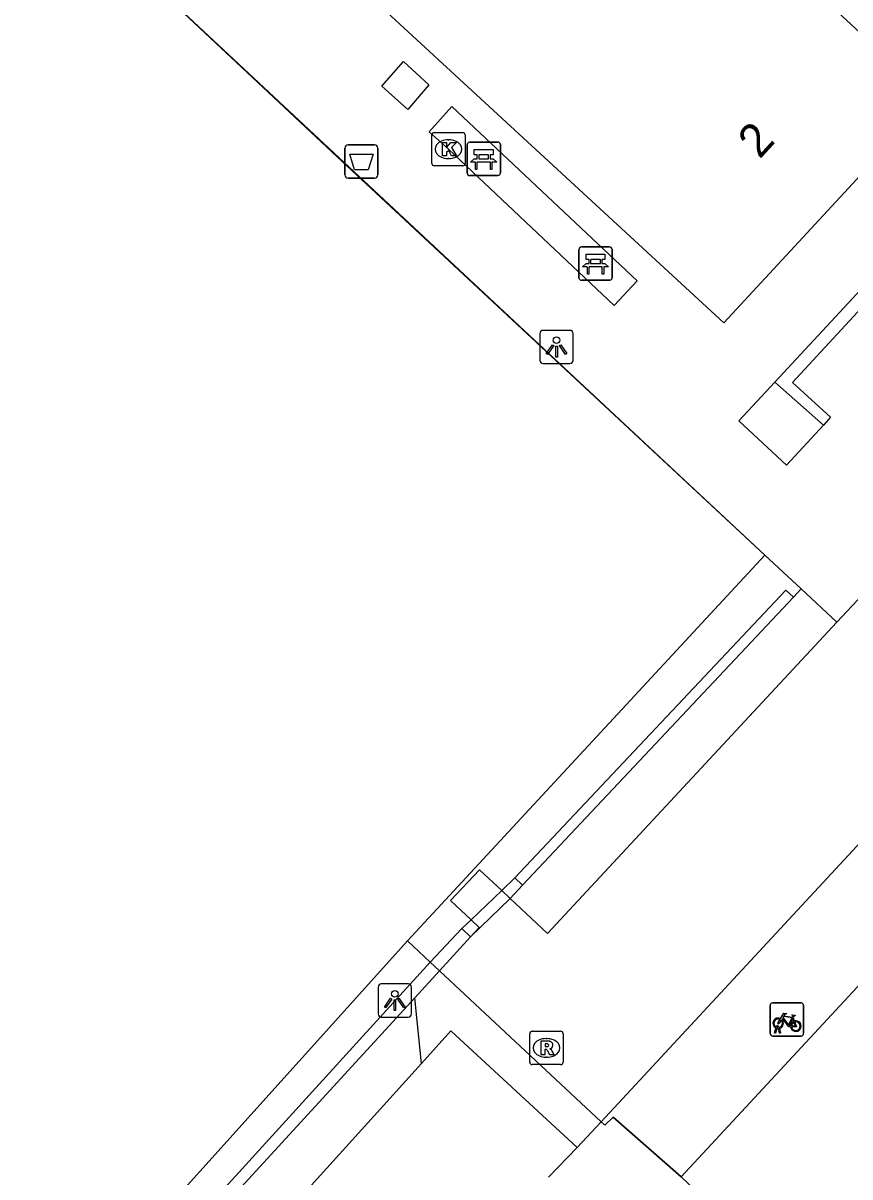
# Model space of a CAD drawing. Extents: x 155640 to 156810, y 382822 to 384046.
# Drawn here: x 156212.63 to 156237.43, y 383263.35 to 383297.97 of the extents above; entities that cross this region are included whole.
import ezdxf

# ---------------------------------------------------------------- set-up
doc = ezdxf.new("R2010")
doc.units = 0
for name, color, linetype in [('IMGEO_Afvalbak', 7, 'Continuous'), ('IMGEO_Bank', 7, 'Continuous'), ('IMGEO_Fietsenrek', 7, 'Continuous'), ('IMGEO_Groenvoorziening', 7, 'Continuous'), ('IMGEO_Haag', 7, 'Continuous'), ('IMGEO_Hek', 7, 'Continuous'), ('IMGEO_Kolk', 7, 'Continuous'), ('IMGEO_Lichtpunt', 7, 'Continuous'), ('IMGEO_Pand', 7, 'Continuous'), ('IMGEO_Pand_nummerreeks', 7, 'Continuous'), ('IMGEO_Rijbaan_lokaal_gesloten', 7, 'Continuous'), ('IMGEO_Rioolput', 7, 'Continuous'), ('IMGEO_Voetpad_op_trap', 7, 'Continuous'), ('IMGEO_Voetpad_open', 7, 'Continuous')]:
    doc.layers.add(name, color=color, linetype=linetype)

msp = doc.modelspace()

# ---------------------------------------------------------------- linework, layer by layer
at = {"layer": 'IMGEO_Afvalbak'}
for p, q in [((156222.383, 383294.317), (156223.173, 383294.317)), ((156223.173, 383294.317), (156222.383, 383294.317)), ((156222.283, 383293.417), (156222.283, 383294.217)), ((156222.283, 383294.217), (156222.283, 383293.417)), ((156223.273, 383294.217), (156223.273, 383293.417)), ((156223.273, 383293.417), (156223.273, 383294.217)), ((156223.173, 383293.317), (156222.383, 383293.317)), ((156222.383, 383293.317), (156223.173, 383293.317))]:
    msp.add_line(p, q, dxfattribs=at)
msp.add_lwpolyline([(156222.426, 383294.031), (156223.13, 383294.031), (156222.981, 383293.561), (156222.575, 383293.561), (156222.426, 383294.031)], dxfattribs=at)
for centre, start, end in [((156222.383, 383294.217), 90, 180), ((156222.383, 383294.217), 90, 180), ((156223.173, 383294.217), 0, 90), ((156223.173, 383294.217), 360, 90), ((156222.383, 383293.417), 180, 270), ((156222.383, 383293.417), 180, 270), ((156223.173, 383293.417), 270, 0), ((156223.173, 383293.417), 270, 0)]:
    msp.add_arc(centre, 0.1, start, end, dxfattribs=at)
at = {"layer": 'IMGEO_Bank'}
for p, q in [((156225.946, 383293.471), (156225.946, 383294.312)), ((156225.946, 383294.312), (156225.946, 383293.471)), ((156226.021, 383294.396), (156226.862, 383294.396)), ((156226.862, 383294.396), (156226.021, 383294.396)), ((156226.946, 383294.321), (156226.946, 383293.48)), ((156226.946, 383293.48), (156226.946, 383294.321)), ((156226.255, 383293.902), (156226.255, 383294.008)), ((156226.299, 383294.008), (156226.299, 383293.902)), ((156226.587, 383294.014), (156226.305, 383294.014)), ((156226.593, 383293.902), (156226.593, 383294.008)), ((156226.637, 383294.008), (156226.637, 383293.902)), ((156226.643, 383293.794), (156226.25, 383293.794)), ((156226.305, 383293.896), (156226.587, 383293.896)), ((156226.871, 383293.396), (156226.03, 383293.396)), ((156226.03, 383293.396), (156226.871, 383293.396)), ((156229.301, 383290.328), (156229.301, 383291.169)), ((156229.301, 383291.169), (156229.301, 383290.328)), ((156229.376, 383291.253), (156230.217, 383291.253)), ((156230.217, 383291.253), (156229.376, 383291.253)), ((156230.301, 383291.178), (156230.301, 383290.337)), ((156230.301, 383290.337), (156230.301, 383291.178)), ((156229.61, 383290.759), (156229.61, 383290.865)), ((156229.654, 383290.865), (156229.654, 383290.759)), ((156229.942, 383290.871), (156229.66, 383290.871)), ((156229.948, 383290.759), (156229.948, 383290.865)), ((156229.992, 383290.865), (156229.992, 383290.759)), ((156229.998, 383290.651), (156229.605, 383290.651)), ((156229.66, 383290.753), (156229.942, 383290.753)), ((156230.226, 383290.253), (156229.385, 383290.253)), ((156229.385, 383290.253), (156230.226, 383290.253))]:
    msp.add_line(p, q, dxfattribs=at)
for points in [[(156226.249, 383294.014), (156226.163, 383294.014), (156226.163, 383294.175), (156226.726, 383294.175), (156226.726, 383294.014), (156226.643, 383294.014)], [(156226.193, 383293.794), (156226.051, 383293.794), (156226.163, 383293.896), (156226.249, 383293.896)], [(156226.243, 383293.787), (156226.243, 383293.58), (156226.2, 383293.58), (156226.2, 383293.787)], [(156226.643, 383293.896), (156226.726, 383293.896), (156226.838, 383293.794), (156226.699, 383293.794)], [(156226.693, 383293.787), (156226.693, 383293.58), (156226.649, 383293.58), (156226.649, 383293.787)], [(156229.604, 383290.871), (156229.518, 383290.871), (156229.518, 383291.032), (156230.081, 383291.032), (156230.081, 383290.871), (156229.998, 383290.871)], [(156229.548, 383290.651), (156229.406, 383290.651), (156229.518, 383290.753), (156229.604, 383290.753)], [(156229.598, 383290.644), (156229.598, 383290.437), (156229.555, 383290.437), (156229.555, 383290.644)], [(156229.998, 383290.753), (156230.081, 383290.753), (156230.193, 383290.651), (156230.054, 383290.651)], [(156230.048, 383290.644), (156230.048, 383290.437), (156230.004, 383290.437), (156230.004, 383290.644)]]:
    msp.add_lwpolyline(points, dxfattribs=at)
for centre, radius, start, end in [((156226.024, 383294.318), 0.0779, 92.4484, 184.2845), ((156226.024, 383294.318), 0.0779, 92.4484, 184.2845), ((156226.868, 383294.318), 0.0779, 2.4484, 94.2845), ((156226.868, 383294.318), 0.0779, 2.4484, 94.2845), ((156226.248, 383294.007), 0.00671, 2.8957, 87.1043), ((156226.305, 383294.007), 0.00671, 92.8957, 177.1043), ((156226.587, 383294.007), 0.00671, 2.8957, 87.1043), ((156226.644, 383294.007), 0.00671, 92.8957, 177.1043), ((156226.193, 383293.787), 0.00671, 2.8957, 87.1043), ((156226.25, 383293.787), 0.00671, 92.8957, 177.1043), ((156226.248, 383293.903), 0.00671, 272.8957, 357.1043), ((156226.305, 383293.903), 0.00671, 182.8957, 267.1043), ((156226.587, 383293.903), 0.00671, 272.8957, 357.1043), ((156226.644, 383293.903), 0.00671, 182.8957, 267.1043), ((156226.642, 383293.787), 0.00671, 2.8957, 87.1043), ((156226.699, 383293.787), 0.00671, 92.8957, 177.1043), ((156226.024, 383293.474), 0.0779, 182.4484, 274.2845), ((156226.024, 383293.474), 0.0779, 182.4484, 274.2845), ((156226.868, 383293.474), 0.0779, 272.4484, 4.2845), ((156226.868, 383293.474), 0.0779, 272.4484, 4.2845), ((156229.379, 383291.175), 0.0779, 92.4484, 184.2845), ((156229.379, 383291.175), 0.0779, 92.4484, 184.2845), ((156230.223, 383291.175), 0.0779, 2.4484, 94.2845), ((156230.223, 383291.175), 0.0779, 2.4484, 94.2845), ((156229.603, 383290.864), 0.00671, 2.8957, 87.1043), ((156229.66, 383290.864), 0.00671, 92.8957, 177.1043), ((156229.942, 383290.864), 0.00671, 2.8957, 87.1043), ((156229.999, 383290.864), 0.00671, 92.8957, 177.1043), ((156229.548, 383290.644), 0.00671, 2.8957, 87.1043), ((156229.605, 383290.644), 0.00671, 92.8957, 177.1043), ((156229.603, 383290.76), 0.00671, 272.8957, 357.1043), ((156229.66, 383290.76), 0.00671, 182.8957, 267.1043), ((156229.942, 383290.76), 0.00671, 272.8957, 357.1043), ((156229.999, 383290.76), 0.00671, 182.8957, 267.1043), ((156229.997, 383290.644), 0.00671, 2.8957, 87.1043), ((156230.054, 383290.644), 0.00671, 92.8957, 177.1043), ((156229.379, 383290.331), 0.0779, 182.4484, 274.2845), ((156229.379, 383290.331), 0.0779, 182.4484, 274.2845), ((156230.223, 383290.331), 0.0779, 272.4484, 4.2845), ((156230.223, 383290.331), 0.0779, 272.4484, 4.2845)]:
    msp.add_arc(centre, radius, start, end, dxfattribs=at)
at = {"layer": 'IMGEO_Fietsenrek'}
for p, q in [((156235.04, 383267.65), (156235.04, 383268.491)), ((156235.04, 383268.491), (156235.04, 383267.65)), ((156235.115, 383268.575), (156235.956, 383268.575)), ((156235.956, 383268.575), (156235.115, 383268.575)), ((156236.04, 383268.5), (156236.04, 383267.659)), ((156236.04, 383267.659), (156236.04, 383268.5)), ((156235.727, 383268.124), (156235.763, 383268.029)), ((156235.167, 383267.659), (156235.206, 383267.819)), ((156235.201, 383267.659), (156235.167, 383267.659)), ((156235.236, 383267.807), (156235.201, 383267.659)), ((156235.278, 383267.831), (156235.277, 383267.835)), ((156235.319, 383267.659), (156235.285, 383267.801)), ((156235.309, 383267.842), (156235.31, 383267.835)), ((156235.317, 383267.805), (156235.352, 383267.659)), ((156235.352, 383267.659), (156235.319, 383267.659)), ((156235.965, 383267.575), (156235.124, 383267.575)), ((156235.124, 383267.575), (156235.965, 383267.575))]:
    msp.add_line(p, q, dxfattribs=at)
for points in [[(156235.374, 383268.049), (156235.322, 383267.959), (156235.282, 383267.934), (156235.283, 383267.981), (156235.338, 383268.075)], [(156235.353, 383268.101), (156235.448, 383268.265), (156235.534, 383268.251), (156235.536, 383268.242), (156235.48, 383268.231), (156235.453, 383268.186), (156235.709, 383268.145)], [(156235.649, 383267.857), (156235.599, 383267.857), (156235.408, 383268.108), (156235.389, 383268.076)], [(156235.696, 383268.12), (156235.439, 383268.161), (156235.422, 383268.132), (156235.589, 383267.912), (156235.696, 383268.12)], [(156235.744, 383268.022), (156235.714, 383268.099), (156235.605, 383267.881), (156235.648, 383267.881)], [(156235.678, 383267.881), (156235.798, 383267.88), (156235.754, 383267.994)], [(156235.774, 383268.001), (156235.829, 383267.856), (156235.679, 383267.856)], [(156235.709, 383268.145), (156235.734, 383268.194), (156235.728, 383268.198), (156235.705, 383268.202), (156235.693, 383268.209), (156235.692, 383268.212), (156235.694, 383268.217), (156235.789, 383268.202), (156235.791, 383268.192), (156235.781, 383268.179), (156235.769, 383268.173), (156235.755, 383268.179), (156235.727, 383268.124)]]:
    msp.add_lwpolyline(points, dxfattribs=at)
for centre, radius, start, end in [((156235.118, 383268.497), 0.0779, 92.4484, 184.2845), ((156235.118, 383268.497), 0.0779, 92.4484, 184.2845), ((156235.962, 383268.497), 0.0779, 2.4484, 94.2845), ((156235.962, 383268.497), 0.0779, 2.4484, 94.2845), ((156235.28, 383267.96), 0.159, 62.6766, 242.1369), ((156235.28, 383267.96), 0.129, 63.3192, 238.903), ((156235.28, 383267.96), 0.129, 283.6043, 43.4302), ((156235.28, 383267.96), 0.159, 283.5766, 46.6042), ((156235.807, 383267.876), 0.159, 113.3408, 178.3217), ((156235.807, 383267.876), 0.159, 187.0065, 105.7708), ((156235.807, 383267.876), 0.129, 113.923, 177.9556), ((156235.807, 383267.876), 0.129, 188.6715, 104.5883), ((156235.118, 383267.653), 0.0779, 182.4484, 274.2845), ((156235.118, 383267.653), 0.0779, 182.4484, 274.2845), ((156235.26, 383267.831), 0.0499, 12.8025, 158.6934), ((156235.28, 383267.96), 0.159, 253.9967, 271.7867), ((156235.26, 383267.831), 0.0174, 12.8025, 163.4502), ((156235.28, 383267.96), 0.129, 253.415, 269.0204), ((156235.962, 383267.653), 0.0779, 272.4484, 4.2845), ((156235.962, 383267.653), 0.0779, 272.4484, 4.2845)]:
    msp.add_arc(centre, radius, start, end, dxfattribs=at)
at = {"layer": 'IMGEO_Groenvoorziening'}
for points in [[(156207.982, 383307.154), (156184.491, 383281.756), (156211.6, 383256.492), (156224.158, 383270.431)], [(156224.158, 383270.431), (156234.882, 383282.008)], [(156235.74, 383280.744), (156235.974, 383280.991)], [(156224.158, 383270.431), (156224.842, 383269.791)], [(156282.79, 383263.589), (156259.014, 383237.928), (156232.367, 383263.357)]]:
    msp.add_lwpolyline(points, dxfattribs=at)
at = {"layer": 'IMGEO_Haag'}
for points in [[(156224.842, 383269.791), (156210.619, 383254.175), (156181.633, 383280.902)], [(156227.383, 383272.321), (156235.514, 383280.957), (156235.74, 383280.744)], [(156227.61, 383272.109), (156235.74, 383280.744)], [(156226.987, 383271.944), (156227.383, 383272.321)], [(156227.241, 383271.705), (156227.61, 383272.109)], [(156227.61, 383272.109), (156227.383, 383272.321)], [(156225.79, 383270.803), (156226.067, 383271.067)], [(156224.842, 383269.791), (156225.79, 383270.803)], [(156225.79, 383270.803), (156226.054, 383270.555)], [(156225.119, 383269.532), (156224.842, 383269.791)], [(156210.637, 383253.749), (156224.377, 383268.721)]]:
    msp.add_lwpolyline(points, dxfattribs=at)
at = {"layer": 'IMGEO_Hek'}
for points in [[(156224.158, 383270.431), (156211.6, 383256.492), (156184.491, 383281.756), (156207.982, 383307.154)], [(156214.588, 383300.953), (156234.882, 383282.008)], [(156232.367, 383263.357), (156255.829, 383288.633), (156268.652, 383276.721)], [(156224.158, 383270.431), (156234.882, 383282.008)], [(156224.158, 383270.431), (156224.842, 383269.791)], [(156224.842, 383269.791), (156225.119, 383269.532)], [(156225.119, 383269.532), (156229.968, 383265.006)], [(156229.968, 383265.006), (156230.078, 383264.903), (156230.326, 383265.146), (156232.367, 383263.357)], [(156282.79, 383263.589), (156259.014, 383237.928), (156232.367, 383263.357)]]:
    msp.add_lwpolyline(points, dxfattribs=at)
at = {"layer": 'IMGEO_Kolk'}
for p, q in [((156224.89, 383293.759), (156224.89, 383294.611)), ((156224.965, 383294.685), (156225.817, 383294.685)), ((156225.891, 383294.611), (156225.891, 383293.759)), ((156225.378, 383294.465), (156225.403, 383294.465)), ((156225.817, 383293.685), (156224.965, 383293.685)), ((156225.401, 383293.905), (156225.376, 383293.905))]:
    msp.add_line(p, q, dxfattribs=at)
for points in [[(156224.89, 383293.759), (156224.89, 383294.611)], [(156224.965, 383294.685), (156225.817, 383294.685)], [(156225.891, 383294.611), (156225.891, 383293.759)], [(156225.211, 383294.385), (156225.334, 383294.385), (156225.334, 383294.234), (156225.464, 383294.385), (156225.628, 383294.385), (156225.482, 383294.234), (156225.635, 383293.985), (156225.483, 383293.985), (156225.398, 383294.149), (156225.334, 383294.082), (156225.334, 383293.985), (156225.211, 383293.985), (156225.211, 383294.385)], [(156225.817, 383293.685), (156224.965, 383293.685)]]:
    msp.add_lwpolyline(points, dxfattribs=at)
for centre, start, end in [((156224.967, 383294.609), 91.552, 178.448), ((156224.967, 383294.609), 91.552, 178.448), ((156225.815, 383294.609), 1.552, 88.448), ((156225.815, 383294.609), 1.552, 88.448), ((156224.967, 383293.761), 181.552, 268.448), ((156224.967, 383293.761), 181.552, 268.448), ((156225.815, 383293.761), 271.552, 358.448), ((156225.815, 383293.761), 271.552, 358.448)]:
    msp.add_arc(centre, 0.0765, start, end, dxfattribs=at)
for centre, major_axis, ratio, start_param, end_param in [((156225.377, 383294.185), (-0.387, 0.002), 0.722429, 4.712389, 7.853982), ((156225.402, 383294.185), (-0.39, 0.002), 0.717154, 1.570796, 4.712389)]:
    msp.add_ellipse(centre, major_axis=major_axis, ratio=ratio, start_param=start_param, end_param=end_param, dxfattribs=at)
at = {"layer": 'IMGEO_Lichtpunt'}
for p, q in [((156229.035, 383288.75), (156228.227, 383288.75)), ((156229.035, 383288.75), (156228.227, 383288.75)), ((156228.133, 383288.655), (156228.133, 383287.848)), ((156228.133, 383288.655), (156228.133, 383287.848)), ((156229.129, 383287.848), (156229.129, 383288.655)), ((156229.129, 383287.848), (156229.129, 383288.655)), ((156228.227, 383287.754), (156229.035, 383287.754)), ((156228.227, 383287.754), (156229.035, 383287.754)), ((156223.28, 383269.047), (156223.28, 383268.24)), ((156223.28, 383269.047), (156223.28, 383268.24)), ((156224.182, 383269.142), (156223.374, 383269.142)), ((156224.182, 383269.142), (156223.374, 383269.142)), ((156224.276, 383268.24), (156224.276, 383269.047)), ((156224.276, 383268.24), (156224.276, 383269.047)), ((156223.374, 383268.146), (156224.182, 383268.146)), ((156223.374, 383268.146), (156224.182, 383268.146))]:
    msp.add_line(p, q, dxfattribs=at)
for points in [[(156228.507, 383288.319), (156228.546, 383288.291), (156228.358, 383288.029), (156228.32, 383288.056), (156228.507, 383288.319)], [(156228.609, 383288.271), (156228.656, 383288.271), (156228.656, 383287.949), (156228.609, 383287.949), (156228.609, 383288.271)], [(156228.719, 383288.291), (156228.757, 383288.318), (156228.944, 383288.056), (156228.905, 383288.028), (156228.719, 383288.291)], [(156223.654, 383268.711), (156223.693, 383268.683), (156223.505, 383268.421), (156223.467, 383268.448), (156223.654, 383268.711)], [(156223.756, 383268.663), (156223.803, 383268.663), (156223.803, 383268.341), (156223.756, 383268.341), (156223.756, 383268.663)], [(156223.866, 383268.683), (156223.904, 383268.71), (156224.091, 383268.448), (156224.052, 383268.42), (156223.866, 383268.683)]]:
    msp.add_lwpolyline(points, dxfattribs=at)
for centre in [(156228.632, 383288.453), (156223.779, 383268.845)]:
    msp.add_circle(centre, 0.0994, dxfattribs=at)
for centre, start, end in [((156228.227, 383288.655), 90, 180), ((156228.227, 383288.655), 90, 180), ((156229.035, 383288.655), 0, 90), ((156229.035, 383288.655), 0, 90), ((156228.227, 383287.848), 180, 270), ((156228.227, 383287.848), 180, 270), ((156229.035, 383287.848), 270, 0), ((156229.035, 383287.848), 270, 360), ((156223.374, 383269.047), 90, 180), ((156223.374, 383269.047), 90, 180), ((156224.182, 383269.047), 0, 90), ((156224.182, 383269.047), 0, 90), ((156223.374, 383268.24), 180, 270), ((156223.374, 383268.24), 180, 270), ((156224.182, 383268.24), 270, 0), ((156224.182, 383268.24), 270, 360)]:
    msp.add_arc(centre, 0.0946, start, end, dxfattribs=at)
at = {"layer": 'IMGEO_Pand'}
msp.add_lwpolyline([(156230.318, 383303.16), (156230.424, 383303.062), (156231.102, 383303.797), (156232.207, 383302.778), (156237.342, 383298.044), (156239.878, 383295.706), (156233.654, 383288.973), (156222.769, 383299.019)], dxfattribs=at)
at = {"layer": 'IMGEO_Rijbaan_lokaal_gesloten'}
for points in [[(156229.248, 383264.232), (156225.464, 383267.736), (156224.577, 383266.755)], [(156224.577, 383266.755), (156215.589, 383256.815)], [(156228.393, 383263.345), (156229.248, 383264.232)]]:
    msp.add_lwpolyline(points, dxfattribs=at)
at = {"layer": 'IMGEO_Rioolput'}
for p, q in [((156227.827, 383266.795), (156227.827, 383267.647)), ((156227.902, 383267.721), (156228.754, 383267.721)), ((156228.828, 383267.647), (156228.828, 383266.795)), ((156228.315, 383267.501), (156228.34, 383267.501)), ((156228.338, 383266.941), (156228.313, 383266.941)), ((156228.754, 383266.721), (156227.902, 383266.721))]:
    msp.add_line(p, q, dxfattribs=at)
for points in [[(156227.827, 383266.795), (156227.827, 383267.647)], [(156227.902, 383267.721), (156228.754, 383267.721)], [(156228.828, 383267.647), (156228.828, 383266.795)], [(156228.416, 383267.419), (156228.164, 383267.421), (156228.164, 383267.021)], [(156228.342, 383267.34), (156228.288, 383267.34), (156228.288, 383267.259)], [(156228.288, 383267.259), (156228.34, 383267.259)], [(156228.164, 383267.021), (156228.288, 383267.021), (156228.288, 383267.183), (156228.299, 383267.183)], [(156228.346, 383267.154), (156228.417, 383267.021), (156228.557, 383267.021), (156228.492, 383267.147)], [(156228.754, 383266.721), (156227.902, 383266.721)]]:
    msp.add_lwpolyline(points, dxfattribs=at)
for centre, radius, start, end in [((156227.904, 383267.645), 0.0765, 91.552, 178.448), ((156227.904, 383267.645), 0.0765, 91.552, 178.448), ((156228.752, 383267.645), 0.0765, 1.552, 88.448), ((156228.752, 383267.645), 0.0765, 1.552, 88.448), ((156228.324, 383267.448), 0.19, 274.7715, 282.9687), ((156228.348, 383267.244), 0.0964, 77.0061, 93.1865), ((156228.362, 383267.301), 0.0378, 276.6634, 79.6772), ((156228.415, 383267.309), 0.109, 350.3612, 89.416), ((156228.413, 383267.309), 0.112, 277.5842, 350.9817), ((156228.298, 383267.13), 0.0533, 26.0293, 88.6989), ((156228.397, 383267.094), 0.108, 29.5134, 73.7905), ((156227.904, 383266.797), 0.0765, 181.552, 268.448), ((156227.904, 383266.797), 0.0765, 181.552, 268.448), ((156228.752, 383266.797), 0.0765, 271.552, 358.448), ((156228.752, 383266.797), 0.0765, 271.552, 358.448)]:
    msp.add_arc(centre, radius, start, end, dxfattribs=at)
for centre, major_axis, ratio, start_param, end_param in [((156228.314, 383267.221), (-0.387, 0.002), 0.722429, 4.712389, 7.853982), ((156228.339, 383267.221), (-0.39, 0.002), 0.717154, 1.570796, 4.712389)]:
    msp.add_ellipse(centre, major_axis=major_axis, ratio=ratio, start_param=start_param, end_param=end_param, dxfattribs=at)
at = {"layer": 'IMGEO_Voetpad_op_trap'}
msp.add_lwpolyline([(156236.64, 383285.907), (156235.177, 383287.192)], dxfattribs=at)
at = {"layer": 'IMGEO_Voetpad_open'}
for points in [[(156214.588, 383300.953), (156222.047, 383293.953), (156234.882, 383282.008)], [(156253.325, 383297.342), (156237.042, 383279.998)], [(156224.166, 383295.376), (156223.394, 383296.071), (156224.037, 383296.818), (156224.798, 383296.115), (156224.166, 383295.376)], [(156231.052, 383290.231), (156230.356, 383289.496), (156225.392, 383294.186), (156224.813, 383294.706), (156225.486, 383295.467), (156231.052, 383290.231)], [(156256.953, 383294.104), (156229.968, 383265.006)], [(156235.177, 383287.192), (156240.872, 383293.328)], [(156242.291, 383292.016), (156242.011, 383291.724), (156240.833, 383292.73), (156235.707, 383287.185), (156236.846, 383286.147), (156236.64, 383285.907)], [(156232.367, 383263.357), (156255.829, 383288.633), (156268.652, 383276.721), (156269.946, 383275.518), (156276.075, 383269.864)], [(156236.64, 383285.907), (156235.527, 383284.709), (156234.099, 383286.031), (156235.177, 383287.192)], [(156234.882, 383282.008), (156235.974, 383280.991)], [(156235.974, 383280.991), (156237.042, 383279.998)], [(156237.042, 383279.998), (156228.361, 383270.65), (156227.241, 383271.705)], [(156226.987, 383271.944), (156226.325, 383272.567), (156225.455, 383271.643), (156226.067, 383271.067)], [(156226.987, 383271.944), (156226.067, 383271.067)], [(156227.241, 383271.705), (156226.987, 383271.944)], [(156227.241, 383271.705), (156226.054, 383270.555)], [(156226.067, 383271.067), (156226.312, 383270.837), (156226.054, 383270.555)], [(156226.054, 383270.555), (156225.119, 383269.532)], [(156224.377, 383268.721), (156225.119, 383269.532)], [(156225.119, 383269.532), (156229.968, 383265.006)], [(156224.577, 383266.755), (156224.377, 383268.721)], [(156229.968, 383265.006), (156229.248, 383264.232)], [(156232.367, 383263.357), (156230.326, 383265.146), (156230.078, 383264.903), (156229.968, 383265.006)]]:
    msp.add_lwpolyline(points, dxfattribs=at)

# ---------------------------------------------------------------- texts
at = {"layer": 'IMGEO_Pand_nummerreeks'}
msp.add_text('2', height=1, rotation=47.5562, dxfattribs=at).set_placement((156234.723, 383293.866))

doc.saveas('drawing.dxf')
